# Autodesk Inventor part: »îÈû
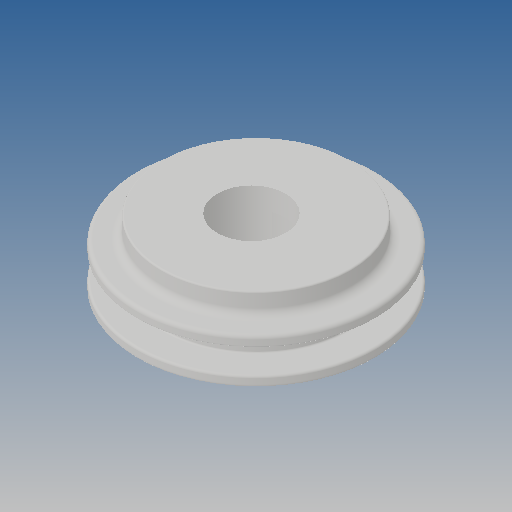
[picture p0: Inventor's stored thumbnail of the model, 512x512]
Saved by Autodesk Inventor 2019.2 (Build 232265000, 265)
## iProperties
Created: 2013-07
Part Number: »îÈû
Material: Ogólny
Document SubType Name: Modeling
Designer: CADENGINEERING4
Density: 1 g/cm^3
Appearance: Domyślna
Author: CADENGINEERING4
Revision Number: ÈÎºÎ
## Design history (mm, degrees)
feature "M10x1.0 ÂÝÎÆ¿×3"
node "Bryła1"
